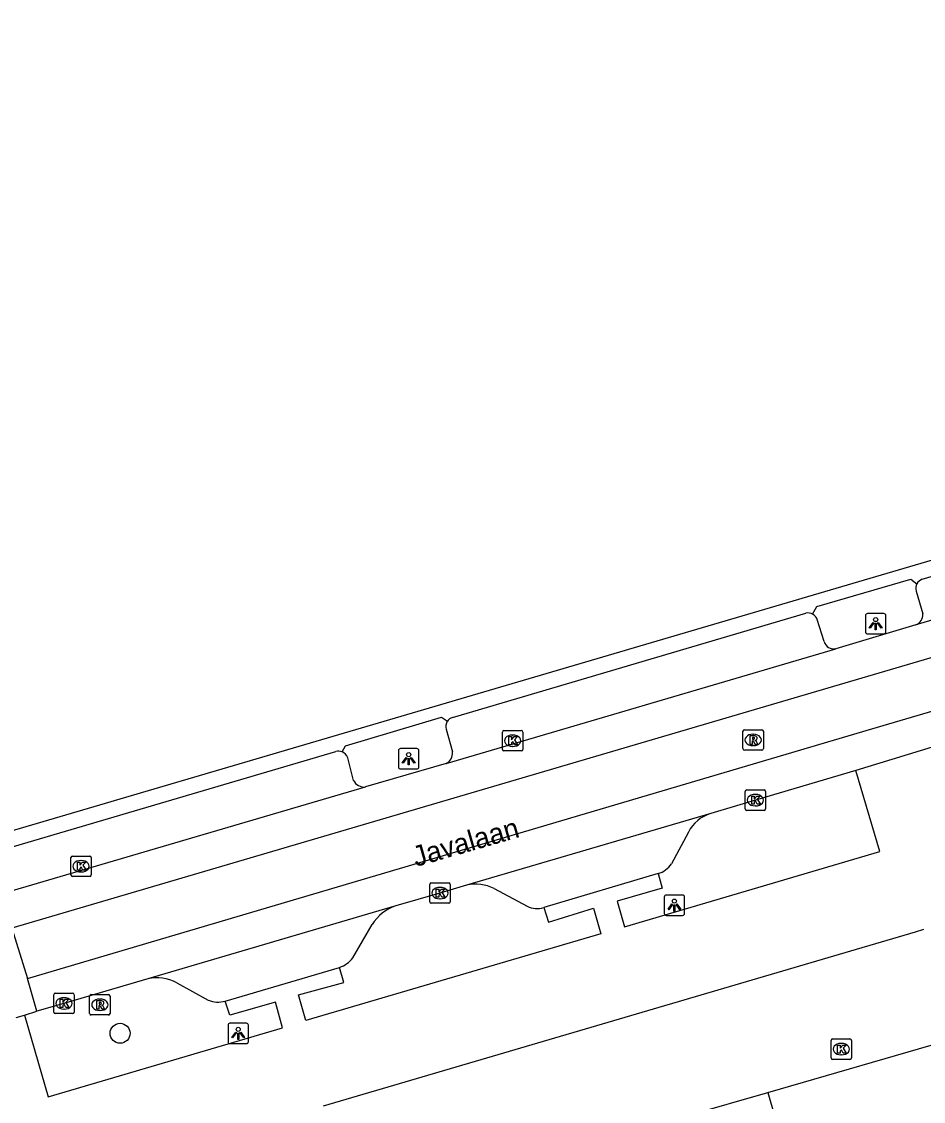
# Model space of a CAD drawing. Extents: x 162417 to 163721, y 384268 to 385416.
# Drawn here: x 162874.2 to 162918.4, y 384558.2 to 384611.2 of the extents above; entities that cross this region are included whole.
import ezdxf

# ---------------------------------------------------------------- set-up
doc = ezdxf.new("R2010")
doc.units = 0
for name, color, linetype in [('IMGEO_Boom', 7, 'Continuous'), ('IMGEO_Hek', 7, 'Continuous'), ('IMGEO_Kolk', 7, 'Continuous'), ('IMGEO_Lichtpunt', 7, 'Continuous'), ('IMGEO_Openbare_ruimte_label', 7, 'Continuous'), ('IMGEO_Pand', 7, 'Continuous'), ('IMGEO_Parkeervlak_open', 7, 'Continuous'), ('IMGEO_Rijbaan_lokaal_gesloten', 7, 'Continuous'), ('IMGEO_Rijbaan_lokaal_open', 7, 'Continuous'), ('IMGEO_Rioolput', 7, 'Continuous'), ('IMGEO_Voetpad_open', 7, 'Continuous')]:
    doc.layers.add(name, color=color, linetype=linetype)

msp = doc.modelspace()

# ---------------------------------------------------------------- linework, layer by layer
at = {"layer": 'IMGEO_Boom'}
msp.add_circle((162879.026, 384561.563), 0.489, dxfattribs=at)
at = {"layer": 'IMGEO_Hek'}
msp.add_lwpolyline([(162910.81, 384558.667), (162919.95, 384561.313)], dxfattribs=at)
at = {"layer": 'IMGEO_Kolk'}
for p, q in [((162897.785, 384575.486), (162897.785, 384576.338)), ((162897.86, 384576.412), (162898.712, 384576.412)), ((162898.273, 384576.192), (162898.298, 384576.192)), ((162898.786, 384576.338), (162898.786, 384575.486)), ((162898.712, 384575.412), (162897.86, 384575.412)), ((162898.296, 384575.632), (162898.271, 384575.632)), ((162909.694, 384572.571), (162909.694, 384573.423)), ((162909.769, 384573.497), (162910.621, 384573.497)), ((162910.182, 384573.277), (162910.207, 384573.277)), ((162910.695, 384573.423), (162910.695, 384572.571)), ((162910.205, 384572.717), (162910.18, 384572.717)), ((162910.621, 384572.497), (162909.769, 384572.497)), ((162876.611, 384569.33), (162876.611, 384570.182)), ((162876.686, 384570.256), (162877.538, 384570.256)), ((162877.612, 384570.182), (162877.612, 384569.33)), ((162877.099, 384570.036), (162877.124, 384570.036)), ((162877.538, 384569.256), (162876.686, 384569.256)), ((162877.122, 384569.476), (162877.097, 384569.476)), ((162894.22, 384568.013), (162894.22, 384568.865)), ((162894.295, 384568.939), (162895.147, 384568.939)), ((162894.708, 384568.719), (162894.733, 384568.719)), ((162895.221, 384568.865), (162895.221, 384568.013)), ((162894.731, 384568.159), (162894.706, 384568.159)), ((162895.147, 384567.939), (162894.295, 384567.939)), ((162875.772, 384562.604), (162875.772, 384563.456)), ((162875.847, 384563.53), (162876.699, 384563.53)), ((162876.26, 384563.31), (162876.285, 384563.31)), ((162876.773, 384563.456), (162876.773, 384562.604)), ((162876.283, 384562.75), (162876.258, 384562.75)), ((162876.699, 384562.53), (162875.847, 384562.53)), ((162913.909, 384560.359), (162913.909, 384561.211)), ((162913.984, 384561.285), (162914.836, 384561.285)), ((162914.397, 384561.065), (162914.422, 384561.065)), ((162914.91, 384561.211), (162914.91, 384560.359)), ((162914.836, 384560.285), (162913.984, 384560.285)), ((162914.42, 384560.505), (162914.395, 384560.505))]:
    msp.add_line(p, q, dxfattribs=at)
for points in [[(162897.785, 384575.486), (162897.785, 384576.338)], [(162897.86, 384576.412), (162898.712, 384576.412)], [(162898.106, 384576.112), (162898.229, 384576.112), (162898.229, 384575.961), (162898.359, 384576.112), (162898.523, 384576.112), (162898.377, 384575.961), (162898.53, 384575.712), (162898.378, 384575.712), (162898.293, 384575.876), (162898.229, 384575.809), (162898.229, 384575.712), (162898.106, 384575.712), (162898.106, 384576.112)], [(162898.786, 384576.338), (162898.786, 384575.486)], [(162898.712, 384575.412), (162897.86, 384575.412)], [(162909.694, 384572.571), (162909.694, 384573.423)], [(162909.769, 384573.497), (162910.621, 384573.497)], [(162910.695, 384573.423), (162910.695, 384572.571)], [(162910.015, 384573.197), (162910.138, 384573.197), (162910.138, 384573.046), (162910.268, 384573.197), (162910.432, 384573.197), (162910.286, 384573.046), (162910.439, 384572.797), (162910.287, 384572.797), (162910.202, 384572.961), (162910.138, 384572.894), (162910.138, 384572.797), (162910.015, 384572.797), (162910.015, 384573.197)], [(162910.621, 384572.497), (162909.769, 384572.497)], [(162876.611, 384569.33), (162876.611, 384570.182)], [(162876.686, 384570.256), (162877.538, 384570.256)], [(162877.612, 384570.182), (162877.612, 384569.33)], [(162876.932, 384569.956), (162877.055, 384569.956), (162877.055, 384569.805), (162877.185, 384569.956), (162877.349, 384569.956), (162877.203, 384569.805), (162877.356, 384569.556), (162877.204, 384569.556), (162877.119, 384569.72), (162877.055, 384569.653), (162877.055, 384569.556), (162876.932, 384569.556), (162876.932, 384569.956)], [(162877.538, 384569.256), (162876.686, 384569.256)], [(162894.22, 384568.013), (162894.22, 384568.865)], [(162894.295, 384568.939), (162895.147, 384568.939)], [(162894.541, 384568.639), (162894.664, 384568.639), (162894.664, 384568.488), (162894.794, 384568.639), (162894.958, 384568.639), (162894.812, 384568.488), (162894.965, 384568.239), (162894.813, 384568.239), (162894.728, 384568.403), (162894.664, 384568.336), (162894.664, 384568.239), (162894.541, 384568.239), (162894.541, 384568.639)], [(162895.221, 384568.865), (162895.221, 384568.013)], [(162895.147, 384567.939), (162894.295, 384567.939)], [(162875.772, 384562.604), (162875.772, 384563.456)], [(162875.847, 384563.53), (162876.699, 384563.53)], [(162876.093, 384563.23), (162876.216, 384563.23), (162876.216, 384563.079), (162876.346, 384563.23), (162876.51, 384563.23), (162876.364, 384563.079), (162876.517, 384562.83), (162876.365, 384562.83), (162876.28, 384562.994), (162876.216, 384562.927), (162876.216, 384562.83), (162876.093, 384562.83), (162876.093, 384563.23)], [(162876.773, 384563.456), (162876.773, 384562.604)], [(162876.699, 384562.53), (162875.847, 384562.53)], [(162913.909, 384560.359), (162913.909, 384561.211)], [(162913.984, 384561.285), (162914.836, 384561.285)], [(162914.91, 384561.211), (162914.91, 384560.359)], [(162914.23, 384560.985), (162914.353, 384560.985), (162914.353, 384560.834), (162914.483, 384560.985), (162914.647, 384560.985), (162914.501, 384560.834), (162914.654, 384560.585), (162914.502, 384560.585), (162914.417, 384560.749), (162914.353, 384560.682), (162914.353, 384560.585), (162914.23, 384560.585), (162914.23, 384560.985)], [(162914.836, 384560.285), (162913.984, 384560.285)]]:
    msp.add_lwpolyline(points, dxfattribs=at)
for centre, start, end in [((162897.862, 384576.336), 91.552, 178.448), ((162897.862, 384576.336), 91.552, 178.448), ((162898.71, 384576.336), 1.552, 88.448), ((162898.71, 384576.336), 1.552, 88.448), ((162897.862, 384575.488), 181.552, 268.448), ((162897.862, 384575.488), 181.552, 268.448), ((162898.71, 384575.488), 271.552, 358.448), ((162898.71, 384575.488), 271.552, 358.448), ((162909.771, 384573.421), 91.552, 178.448), ((162909.771, 384573.421), 91.552, 178.448), ((162910.619, 384573.421), 1.552, 88.448), ((162910.619, 384573.421), 1.552, 88.448), ((162909.771, 384572.573), 181.552, 268.448), ((162909.771, 384572.573), 181.552, 268.448), ((162910.619, 384572.573), 271.552, 358.448), ((162910.619, 384572.573), 271.552, 358.448), ((162876.688, 384570.18), 91.552, 178.448), ((162876.688, 384570.18), 91.552, 178.448), ((162877.536, 384570.18), 1.552, 88.448), ((162877.536, 384570.18), 1.552, 88.448), ((162876.688, 384569.332), 181.552, 268.448), ((162876.688, 384569.332), 181.552, 268.448), ((162877.536, 384569.332), 271.552, 358.448), ((162877.536, 384569.332), 271.552, 358.448), ((162894.297, 384568.863), 91.552, 178.448), ((162894.297, 384568.863), 91.552, 178.448), ((162895.145, 384568.863), 1.552, 88.448), ((162895.145, 384568.863), 1.552, 88.448), ((162894.297, 384568.015), 181.552, 268.448), ((162894.297, 384568.015), 181.552, 268.448), ((162895.145, 384568.015), 271.552, 358.448), ((162895.145, 384568.015), 271.552, 358.448), ((162875.849, 384563.454), 91.552, 178.448), ((162875.849, 384563.454), 91.552, 178.448), ((162876.697, 384563.454), 1.552, 88.448), ((162876.697, 384563.454), 1.552, 88.448), ((162875.849, 384562.606), 181.552, 268.448), ((162875.849, 384562.606), 181.552, 268.448), ((162876.697, 384562.606), 271.552, 358.448), ((162876.697, 384562.606), 271.552, 358.448), ((162913.986, 384561.209), 91.552, 178.448), ((162913.986, 384561.209), 91.552, 178.448), ((162914.834, 384561.209), 1.552, 88.448), ((162914.834, 384561.209), 1.552, 88.448), ((162913.986, 384560.361), 181.552, 268.448), ((162913.986, 384560.361), 181.552, 268.448), ((162914.834, 384560.361), 271.552, 358.448), ((162914.834, 384560.361), 271.552, 358.448)]:
    msp.add_arc(centre, 0.0765, start, end, dxfattribs=at)
for centre, major_axis, ratio, start_param, end_param in [((162898.272, 384575.912), (-0.387, 0.002), 0.722429, 4.712389, 7.853982), ((162898.297, 384575.912), (-0.39, 0.002), 0.717154, 1.570796, 4.712389), ((162910.181, 384572.997), (-0.387, 0.002), 0.722429, 4.712389, 7.853982), ((162910.206, 384572.997), (-0.39, 0.002), 0.717154, 1.570796, 4.712389), ((162877.098, 384569.756), (-0.387, 0.002), 0.722429, 4.712389, 7.853982), ((162877.123, 384569.756), (-0.39, 0.002), 0.717154, 1.570796, 4.712389), ((162894.707, 384568.439), (-0.387, 0.002), 0.722429, 4.712389, 7.853982), ((162894.732, 384568.439), (-0.39, 0.002), 0.717154, 1.570796, 4.712389), ((162876.259, 384563.03), (-0.387, 0.002), 0.722429, 4.712389, 7.853982), ((162876.284, 384563.03), (-0.39, 0.002), 0.717154, 1.570796, 4.712389), ((162914.396, 384560.785), (-0.387, 0.002), 0.722429, 4.712389, 7.853982), ((162914.421, 384560.785), (-0.39, 0.002), 0.717154, 1.570796, 4.712389)]:
    msp.add_ellipse(centre, major_axis=major_axis, ratio=ratio, start_param=start_param, end_param=end_param, dxfattribs=at)
at = {"layer": 'IMGEO_Lichtpunt'}
for p, q in [((162915.599, 384582.054), (162915.599, 384581.247)), ((162915.599, 384582.054), (162915.599, 384581.247)), ((162916.501, 384582.149), (162915.693, 384582.149)), ((162916.501, 384582.149), (162915.693, 384582.149)), ((162916.595, 384581.247), (162916.595, 384582.054)), ((162916.595, 384581.247), (162916.595, 384582.054)), ((162915.693, 384581.153), (162916.501, 384581.153)), ((162915.693, 384581.153), (162916.501, 384581.153)), ((162892.686, 384575.431), (162892.686, 384574.624)), ((162892.686, 384575.431), (162892.686, 384574.624)), ((162893.588, 384575.526), (162892.78, 384575.526)), ((162893.588, 384575.526), (162892.78, 384575.526)), ((162893.682, 384574.624), (162893.682, 384575.431)), ((162893.682, 384574.624), (162893.682, 384575.431)), ((162892.78, 384574.53), (162893.588, 384574.53)), ((162892.78, 384574.53), (162893.588, 384574.53)), ((162905.723, 384568.247), (162905.723, 384567.44)), ((162905.723, 384568.247), (162905.723, 384567.44)), ((162906.625, 384568.342), (162905.817, 384568.342)), ((162906.625, 384568.342), (162905.817, 384568.342)), ((162906.719, 384567.44), (162906.719, 384568.247)), ((162906.719, 384567.44), (162906.719, 384568.247)), ((162905.817, 384567.346), (162906.625, 384567.346)), ((162905.817, 384567.346), (162906.625, 384567.346)), ((162884.323, 384561.96), (162884.323, 384561.153)), ((162884.323, 384561.96), (162884.323, 384561.153)), ((162885.225, 384562.055), (162884.417, 384562.055)), ((162885.225, 384562.055), (162884.417, 384562.055)), ((162885.319, 384561.153), (162885.319, 384561.96)), ((162885.319, 384561.153), (162885.319, 384561.96)), ((162884.417, 384561.059), (162885.225, 384561.059)), ((162884.417, 384561.059), (162885.225, 384561.059))]:
    msp.add_line(p, q, dxfattribs=at)
for points in [[(162915.973, 384581.718), (162916.012, 384581.69), (162915.824, 384581.428), (162915.786, 384581.455), (162915.973, 384581.718)], [(162916.185, 384581.69), (162916.223, 384581.717), (162916.41, 384581.455), (162916.371, 384581.427), (162916.185, 384581.69)], [(162916.075, 384581.67), (162916.122, 384581.67), (162916.122, 384581.348), (162916.075, 384581.348), (162916.075, 384581.67)], [(162893.06, 384575.095), (162893.099, 384575.067), (162892.911, 384574.805), (162892.873, 384574.832), (162893.06, 384575.095)], [(162893.162, 384575.047), (162893.209, 384575.047), (162893.209, 384574.725), (162893.162, 384574.725), (162893.162, 384575.047)], [(162893.272, 384575.067), (162893.31, 384575.094), (162893.497, 384574.832), (162893.458, 384574.804), (162893.272, 384575.067)], [(162906.097, 384567.911), (162906.136, 384567.883), (162905.948, 384567.621), (162905.91, 384567.648), (162906.097, 384567.911)], [(162906.199, 384567.863), (162906.246, 384567.863), (162906.246, 384567.541), (162906.199, 384567.541), (162906.199, 384567.863)], [(162906.309, 384567.883), (162906.347, 384567.91), (162906.534, 384567.648), (162906.495, 384567.62), (162906.309, 384567.883)], [(162884.697, 384561.624), (162884.736, 384561.596), (162884.548, 384561.334), (162884.51, 384561.361), (162884.697, 384561.624)], [(162884.909, 384561.596), (162884.947, 384561.623), (162885.134, 384561.361), (162885.095, 384561.333), (162884.909, 384561.596)], [(162884.799, 384561.576), (162884.846, 384561.576), (162884.846, 384561.254), (162884.799, 384561.254), (162884.799, 384561.576)]]:
    msp.add_lwpolyline(points, dxfattribs=at)
for centre in [(162916.098, 384581.852), (162893.185, 384575.229), (162906.222, 384568.045), (162884.822, 384561.758)]:
    msp.add_circle(centre, 0.0994, dxfattribs=at)
for centre, start, end in [((162915.693, 384582.054), 90, 180), ((162915.693, 384582.054), 90, 180), ((162916.501, 384582.054), 0, 90), ((162916.501, 384582.054), 0, 90), ((162915.693, 384581.247), 180, 270), ((162915.693, 384581.247), 180, 270), ((162916.501, 384581.247), 270, 0), ((162916.501, 384581.247), 270, 360), ((162892.78, 384575.431), 90, 180), ((162892.78, 384575.431), 90, 180), ((162893.588, 384575.431), 0, 90), ((162893.588, 384575.431), 0, 90), ((162892.78, 384574.624), 180, 270), ((162892.78, 384574.624), 180, 270), ((162893.588, 384574.624), 270, 0), ((162893.588, 384574.624), 270, 360), ((162905.817, 384568.247), 90, 180), ((162905.817, 384568.247), 90, 180), ((162906.625, 384568.247), 0, 90), ((162906.625, 384568.247), 0, 90), ((162905.817, 384567.44), 180, 270), ((162905.817, 384567.44), 180, 270), ((162906.625, 384567.44), 270, 0), ((162906.625, 384567.44), 270, 360), ((162884.417, 384561.96), 90, 180), ((162884.417, 384561.96), 90, 180), ((162885.225, 384561.96), 0, 90), ((162885.225, 384561.96), 0, 90), ((162884.417, 384561.153), 180, 270), ((162884.417, 384561.153), 180, 270), ((162885.225, 384561.153), 270, 0), ((162885.225, 384561.153), 270, 360)]:
    msp.add_arc(centre, 0.0946, start, end, dxfattribs=at)
at = {"layer": 'IMGEO_Pand'}
msp.add_lwpolyline([(162910.835, 384544.088), (162883.663, 384536.285), (162879.794, 384549.759), (162910.81, 384558.667), (162913.62, 384548.884), (162909.775, 384547.78), (162910.835, 384544.088)], dxfattribs=at)
at = {"layer": 'IMGEO_Parkeervlak_open'}
for points in [[(162918.083, 384583.253), (162918.414, 384582.129)], [(162913.566, 384580.777), (162913.235, 384581.862)], [(162895.029, 384576.483), (162895.331, 384575.363)], [(162890.472, 384573.966), (162890.198, 384575.073)], [(162906.911, 384571.432), (162906.076, 384569.875)], [(162897.38, 384568.664), (162898.997, 384567.798)], [(162890.443, 384565.266), (162891.392, 384566.893)], [(162881.808, 384564.041), (162883.355, 384563.195)]]:
    msp.add_lwpolyline(points, dxfattribs=at)
for centre, radius, start, end in [((162918.532, 384583.387), 0.468, 151.2964, 196.6191), ((162912.773, 384581.684), 0.495, 21.0296, 61.9347), ((162917.849, 384582.11), 0.565, 292.7661, 1.9352), ((162914.047, 384580.915), 0.501, 196.0546, 281.6134), ((162895.469, 384576.615), 0.46, 147.4011, 196.7189), ((162889.727, 384574.895), 0.503, 20.701, 68.0971), ((162894.791, 384575.29), 0.545, 295.0612, 7.6753), ((162891.004, 384574.239), 0.598, 207.1559, 276.6299), ((162908.54, 384570.59), 1.834, 106.966, 152.6658), ((162905.098, 384570.515), 1.169, 286.2401, 326.7924), ((162896.476, 384566.861), 2.017, 63.3608, 102.7965), ((162893.157, 384565.842), 2.054, 106.8658, 149.2362), ((162899.48, 384568.732), 1.052, 242.6428, 288.377), ((162889.393, 384566.033), 1.301, 288.1078, 323.852), ((162880.867, 384562.373), 1.915, 60.5722, 104.6337), ((162883.838, 384564.296), 1.203, 246.3322, 286.4371)]:
    msp.add_arc(centre, radius, start, end, dxfattribs=at)
at = {"layer": 'IMGEO_Rijbaan_lokaal_gesloten'}
for points in [[(162983.624, 384599.009), (162943.494, 384587.243), (162873.708, 384566.717)], [(162874.476, 384564.25), (162915.904, 384576.492), (162984.351, 384596.62)], [(162937.234, 384587.201), (162918.068, 384581.589)], [(162918.068, 384581.589), (162914.148, 384580.425)], [(162895.022, 384574.797), (162914.148, 384580.425)], [(162919.455, 384575.77), (162915.12, 384574.454)], [(162895.022, 384574.797), (162891.073, 384573.645)], [(162915.12, 384574.454), (162910.195, 384572.997), (162908.005, 384572.344)], [(162873.19, 384568.402), (162891.073, 384573.645)], [(162908.005, 384572.344), (162896.029, 384568.828)], [(162896.029, 384568.828), (162894.721, 384568.439), (162892.561, 384567.808)], [(162892.561, 384567.808), (162880.383, 384564.226)], [(162880.383, 384564.226), (162876.273, 384563.03), (162874.94, 384562.642)]]:
    msp.add_lwpolyline(points, dxfattribs=at)
at = {"layer": 'IMGEO_Rijbaan_lokaal_open'}
for points in [[(162873.708, 384566.717), (162874.476, 384564.25)], [(162874.94, 384562.642), (162874.476, 384564.25)], [(162873.928, 384562.334), (162874.334, 384562.447)], [(162874.334, 384562.447), (162874.94, 384562.642)]]:
    msp.add_lwpolyline(points, dxfattribs=at)
at = {"layer": 'IMGEO_Rioolput'}
for p, q in [((162909.661, 384576.45), (162910.513, 384576.45)), ((162909.586, 384575.524), (162909.586, 384576.376)), ((162910.074, 384576.23), (162910.099, 384576.23)), ((162910.587, 384576.376), (162910.587, 384575.524)), ((162910.513, 384575.45), (162909.661, 384575.45)), ((162910.097, 384575.67), (162910.072, 384575.67)), ((162877.533, 384562.534), (162877.533, 384563.386)), ((162877.608, 384563.46), (162878.46, 384563.46)), ((162878.021, 384563.24), (162878.046, 384563.24)), ((162878.534, 384563.386), (162878.534, 384562.534)), ((162878.044, 384562.68), (162878.019, 384562.68)), ((162878.46, 384562.46), (162877.608, 384562.46))]:
    msp.add_line(p, q, dxfattribs=at)
for points in [[(162909.661, 384576.45), (162910.513, 384576.45)], [(162909.586, 384575.524), (162909.586, 384576.376)], [(162910.175, 384576.148), (162909.923, 384576.15), (162909.923, 384575.75)], [(162909.923, 384575.75), (162910.047, 384575.75), (162910.047, 384575.912), (162910.058, 384575.912)], [(162910.101, 384576.069), (162910.047, 384576.069), (162910.047, 384575.988)], [(162910.047, 384575.988), (162910.099, 384575.988)], [(162910.587, 384576.376), (162910.587, 384575.524)], [(162910.513, 384575.45), (162909.661, 384575.45)], [(162910.105, 384575.883), (162910.176, 384575.75), (162910.316, 384575.75), (162910.251, 384575.876)], [(162877.533, 384562.534), (162877.533, 384563.386)], [(162877.608, 384563.46), (162878.46, 384563.46)], [(162878.534, 384563.386), (162878.534, 384562.534)], [(162878.122, 384563.158), (162877.87, 384563.16), (162877.87, 384562.76)], [(162877.87, 384562.76), (162877.994, 384562.76), (162877.994, 384562.922), (162878.005, 384562.922)], [(162878.048, 384563.079), (162877.994, 384563.079), (162877.994, 384562.998)], [(162877.994, 384562.998), (162878.046, 384562.998)], [(162878.052, 384562.893), (162878.123, 384562.76), (162878.263, 384562.76), (162878.198, 384562.886)], [(162878.46, 384562.46), (162877.608, 384562.46)]]:
    msp.add_lwpolyline(points, dxfattribs=at)
for centre, radius, start, end in [((162909.663, 384576.374), 0.0765, 91.552, 178.448), ((162909.663, 384576.374), 0.0765, 91.552, 178.448), ((162910.511, 384576.374), 0.0765, 1.552, 88.448), ((162910.511, 384576.374), 0.0765, 1.552, 88.448), ((162910.057, 384575.859), 0.0533, 26.0293, 88.6989), ((162910.083, 384576.177), 0.19, 274.7715, 282.9687), ((162910.107, 384575.973), 0.0964, 77.0061, 93.1865), ((162910.121, 384576.03), 0.0378, 276.6634, 79.6772), ((162910.174, 384576.038), 0.109, 350.3612, 89.416), ((162910.172, 384576.038), 0.112, 277.5842, 350.9817), ((162910.156, 384575.823), 0.108, 29.5134, 73.7905), ((162909.663, 384575.526), 0.0765, 181.552, 268.448), ((162909.663, 384575.526), 0.0765, 181.552, 268.448), ((162910.511, 384575.526), 0.0765, 271.552, 358.448), ((162910.511, 384575.526), 0.0765, 271.552, 358.448), ((162877.61, 384563.384), 0.0765, 91.552, 178.448), ((162877.61, 384563.384), 0.0765, 91.552, 178.448), ((162878.458, 384563.384), 0.0765, 1.552, 88.448), ((162878.458, 384563.384), 0.0765, 1.552, 88.448), ((162878.004, 384562.869), 0.0533, 26.0293, 88.6989), ((162878.03, 384563.187), 0.19, 274.7715, 282.9687), ((162878.054, 384562.983), 0.0964, 77.0061, 93.1865), ((162878.068, 384563.04), 0.0378, 276.6634, 79.6772), ((162878.121, 384563.048), 0.109, 350.3612, 89.416), ((162878.119, 384563.048), 0.112, 277.5842, 350.9817), ((162878.103, 384562.833), 0.108, 29.5134, 73.7905), ((162877.61, 384562.536), 0.0765, 181.552, 268.448), ((162877.61, 384562.536), 0.0765, 181.552, 268.448), ((162878.458, 384562.536), 0.0765, 271.552, 358.448), ((162878.458, 384562.536), 0.0765, 271.552, 358.448)]:
    msp.add_arc(centre, radius, start, end, dxfattribs=at)
for centre, major_axis, ratio, start_param, end_param in [((162910.073, 384575.95), (-0.387, 0.002), 0.722429, 4.712389, 7.853982), ((162910.098, 384575.95), (-0.39, 0.002), 0.717154, 1.570796, 4.712389), ((162878.02, 384562.96), (-0.387, 0.002), 0.722429, 4.712389, 7.853982), ((162878.045, 384562.96), (-0.39, 0.002), 0.717154, 1.570796, 4.712389)]:
    msp.add_ellipse(centre, major_axis=major_axis, ratio=ratio, start_param=start_param, end_param=end_param, dxfattribs=at)
at = {"layer": 'IMGEO_Voetpad_open'}
for points in [[(163009.008, 384611.181), (162941.602, 384591.456), (162866.154, 384569.262), (162844.124, 384562.781)], [(162918.372, 384583.828), (162935.751, 384588.945)], [(162913.006, 384582.121), (162913.21, 384582.498), (162917.827, 384583.835), (162918.121, 384583.612)], [(162895.329, 384577.053), (162912.675, 384582.166)], [(162889.915, 384575.362), (162890.081, 384575.654), (162894.79, 384577.065), (162895.082, 384576.863)], [(162873.248, 384570.557), (162889.609, 384575.383)], [(162905.425, 384569.393), (162905.626, 384568.681), (162903.413, 384568.044), (162903.771, 384566.782), (162916.3, 384570.475), (162915.12, 384574.454)], [(162905.425, 384569.393), (162899.812, 384567.734)], [(162899.812, 384567.734), (162900.05, 384567.014), (162902.261, 384567.694), (162902.619, 384566.445), (162888.138, 384562.19), (162887.777, 384563.449), (162889.998, 384564.062), (162889.797, 384564.797)], [(162889.014, 384558.009), (162918.058, 384566.545), (162918.465, 384566.665)], [(162884.178, 384563.143), (162889.797, 384564.797)], [(162874.334, 384562.447), (162875.496, 384558.453), (162887.001, 384561.832), (162886.646, 384563.083), (162884.411, 384562.446), (162884.178, 384563.143)]]:
    msp.add_lwpolyline(points, dxfattribs=at)
for centre, radius, start, end in [((162918.533, 384583.387), 0.47, 110.0714, 151.3564), ((162912.779, 384581.693), 0.484, 62.0902, 102.4258), ((162895.466, 384576.619), 0.455, 107.5513, 147.5859), ((162889.73, 384574.907), 0.491, 67.863, 104.2852)]:
    msp.add_arc(centre, radius, start, end, dxfattribs=at)

# ---------------------------------------------------------------- texts
at = {"layer": 'IMGEO_Openbare_ruimte_label'}
msp.add_text('Javalaan', height=1, rotation=16.0792, dxfattribs=at).set_placement((162893.543, 384569.718))

doc.saveas('drawing.dxf')
